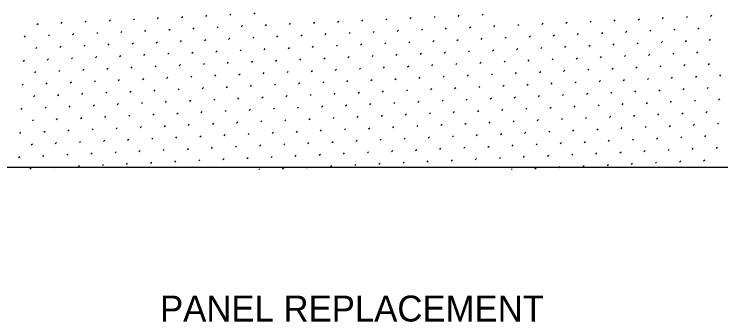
# Model space of a CAD drawing. Extents: x 49991.4 to 50021, y 49987.6 to 50011.4.
# Drawn here: x 50007.726 to 50009.904, y 49993.814 to 49994.763 of the extents above; entities that cross this region are included whole.
import ezdxf

# ---------------------------------------------------------------- set-up
doc = ezdxf.new("R2010")
doc.units = 0
for name, color, linetype in [('Level 1', 7, 'Continuous'), ('Level 10', 7, 'Continuous'), ('Level 2', 7, 'Continuous')]:
    doc.layers.add(name, color=color, linetype=linetype)

msp = doc.modelspace()

# ---------------------------------------------------------------- linework, layer by layer
at = {"layer": 'Level 1'}
msp.add_line((50015.1301, 49994.2903), (50001.3364, 49994.2903), dxfattribs=at)
at = {"layer": 'Level 10'}
for p, q in [((50008.3907, 49994.7596), (50008.3943, 49994.7631)), ((50008.465, 49994.7631), (50008.4685, 49994.7667)), ((50009.1686, 49994.7597), (50009.1721, 49994.7632)), ((50007.9452, 49994.7383), (50007.9487, 49994.7419)), ((50008.0195, 49994.7419), (50008.023, 49994.7454)), ((50008.0937, 49994.7454), (50008.0972, 49994.749)), ((50008.168, 49994.749), (50008.1715, 49994.7525)), ((50008.2422, 49994.7525), (50008.2458, 49994.756)), ((50008.3165, 49994.7561), (50008.32, 49994.7596)), ((50008.7231, 49994.7384), (50008.7266, 49994.7419)), ((50008.7973, 49994.742), (50008.8009, 49994.7455)), ((50008.8716, 49994.7455), (50008.8751, 49994.749)), ((50008.9459, 49994.749), (50008.9494, 49994.7526)), ((50009.0201, 49994.7526), (50009.0236, 49994.7561)), ((50009.0944, 49994.7561), (50009.0979, 49994.7597)), ((50009.501, 49994.7385), (50009.5045, 49994.742)), ((50009.5752, 49994.742), (50009.5788, 49994.7456)), ((50009.6495, 49994.7456), (50009.653, 49994.7491)), ((50009.7237, 49994.7491), (50009.7273, 49994.7526)), ((50009.798, 49994.7527), (50009.8015, 49994.7562)), ((50009.8722, 49994.7562), (50009.8758, 49994.7597)), ((50007.7967, 49994.7313), (50007.8002, 49994.7348)), ((50007.871, 49994.7348), (50007.8745, 49994.7383)), ((50008.2033, 49994.7136), (50008.2069, 49994.7171)), ((50008.2776, 49994.7172), (50008.2811, 49994.7207)), ((50008.3518, 49994.7207), (50008.3554, 49994.7242)), ((50008.4261, 49994.7242), (50008.4296, 49994.7278)), ((50008.5003, 49994.7278), (50008.5039, 49994.7313)), ((50008.5746, 49994.7313), (50008.5781, 49994.7349)), ((50008.6488, 49994.7349), (50008.6524, 49994.7384)), ((50008.9812, 49994.7137), (50008.9847, 49994.7172)), ((50009.0555, 49994.7172), (50009.059, 49994.7208)), ((50009.1297, 49994.7208), (50009.1332, 49994.7243)), ((50009.204, 49994.7243), (50009.2075, 49994.7278)), ((50009.2782, 49994.7279), (50009.2818, 49994.7314)), ((50009.3525, 49994.7314), (50009.356, 49994.7349)), ((50009.4267, 49994.7349), (50009.4303, 49994.7385)), ((50009.7591, 49994.7138), (50009.7626, 49994.7173)), ((50009.8333, 49994.7173), (50009.8369, 49994.7208)), ((50007.7578, 49994.6924), (50007.7613, 49994.6959)), ((50007.8321, 49994.6959), (50007.8356, 49994.6994)), ((50007.9063, 49994.6994), (50007.9098, 49994.703)), ((50007.9806, 49994.703), (50007.9841, 49994.7065)), ((50008.0548, 49994.7065), (50008.0583, 49994.7101)), ((50008.1291, 49994.7101), (50008.1326, 49994.7136)), ((50008.5357, 49994.6924), (50008.5392, 49994.696)), ((50008.6099, 49994.696), (50008.6135, 49994.6995)), ((50008.6842, 49994.6995), (50008.6877, 49994.703)), ((50008.7584, 49994.7031), (50008.762, 49994.7066)), ((50008.8327, 49994.7066), (50008.8362, 49994.7101)), ((50008.907, 49994.7101), (50008.9105, 49994.7137)), ((50009.3136, 49994.6925), (50009.3171, 49994.696)), ((50009.3878, 49994.696), (50009.3914, 49994.6996)), ((50009.4621, 49994.6996), (50009.4656, 49994.7031)), ((50009.5363, 49994.7031), (50009.5399, 49994.7067)), ((50009.6106, 49994.7067), (50009.6141, 49994.7102)), ((50009.6848, 49994.7102), (50009.6884, 49994.7137)), ((50008.0902, 49994.6712), (50008.0937, 49994.6747)), ((50008.1644, 49994.6747), (50008.168, 49994.6783)), ((50008.2387, 49994.6783), (50008.2422, 49994.6818)), ((50008.3129, 49994.6818), (50008.3165, 49994.6853)), ((50008.3872, 49994.6853), (50008.3907, 49994.6889)), ((50008.4614, 49994.6889), (50008.465, 49994.6924)), ((50008.8681, 49994.6712), (50008.8716, 49994.6748)), ((50008.9423, 49994.6748), (50008.9458, 49994.6783)), ((50009.0166, 49994.6783), (50009.0201, 49994.6819)), ((50009.0908, 49994.6819), (50009.0944, 49994.6854)), ((50009.1651, 49994.6854), (50009.1686, 49994.6889)), ((50009.2393, 49994.689), (50009.2429, 49994.6925)), ((50009.6459, 49994.6713), (50009.6495, 49994.6749)), ((50009.7202, 49994.6749), (50009.7237, 49994.6784)), ((50009.7945, 49994.6784), (50009.798, 49994.6819)), ((50009.8687, 49994.6819), (50009.8722, 49994.6855)), ((50007.7932, 49994.657), (50007.7967, 49994.6605)), ((50007.8674, 49994.6605), (50007.8709, 49994.6641)), ((50007.9417, 49994.6641), (50007.9452, 49994.6676)), ((50008.0159, 49994.6676), (50008.0194, 49994.6712)), ((50008.4225, 49994.65), (50008.4261, 49994.6535)), ((50008.4968, 49994.6535), (50008.5003, 49994.6571)), ((50008.571, 49994.6571), (50008.5746, 49994.6606)), ((50008.6453, 49994.6606), (50008.6488, 49994.6642)), ((50008.7195, 49994.6642), (50008.7231, 49994.6677)), ((50008.7938, 49994.6677), (50008.7973, 49994.6712)), ((50009.2004, 49994.6501), (50009.204, 49994.6536)), ((50009.2747, 49994.6536), (50009.2782, 49994.6571)), ((50009.3489, 49994.6571), (50009.3525, 49994.6607)), ((50009.4232, 49994.6607), (50009.4267, 49994.6642)), ((50009.4974, 49994.6642), (50009.501, 49994.6678)), ((50009.5717, 49994.6678), (50009.5752, 49994.6713)), ((50007.977, 49994.6287), (50007.9806, 49994.6323)), ((50008.0513, 49994.6323), (50008.0548, 49994.6358)), ((50008.1255, 49994.6358), (50008.1291, 49994.6394)), ((50008.1998, 49994.6394), (50008.2033, 49994.6429)), ((50008.274, 49994.6429), (50008.2776, 49994.6464)), ((50008.3483, 49994.6464), (50008.3518, 49994.65)), ((50008.7549, 49994.6288), (50008.7584, 49994.6323)), ((50008.8292, 49994.6323), (50008.8327, 49994.6359)), ((50008.9034, 49994.6359), (50008.9069, 49994.6394)), ((50008.9777, 49994.6394), (50008.9812, 49994.643)), ((50009.0519, 49994.643), (50009.0555, 49994.6465)), ((50009.1262, 49994.6465), (50009.1297, 49994.6501)), ((50009.5328, 49994.6289), (50009.5363, 49994.6324)), ((50009.607, 49994.6324), (50009.6106, 49994.636)), ((50009.6813, 49994.636), (50009.6848, 49994.6395)), ((50009.7556, 49994.6395), (50009.7591, 49994.643)), ((50009.8298, 49994.643), (50009.8333, 49994.6466)), ((50007.7543, 49994.6181), (50007.7578, 49994.6216)), ((50007.8285, 49994.6216), (50007.832, 49994.6252)), ((50007.9028, 49994.6252), (50007.9063, 49994.6287)), ((50008.3094, 49994.6075), (50008.3129, 49994.6111)), ((50008.3836, 49994.6111), (50008.3872, 49994.6146)), ((50008.4579, 49994.6146), (50008.4614, 49994.6182)), ((50008.5321, 49994.6182), (50008.5357, 49994.6217)), ((50008.6064, 49994.6217), (50008.6099, 49994.6253)), ((50008.6807, 49994.6253), (50008.6842, 49994.6288)), ((50009.0873, 49994.6076), (50009.0908, 49994.6112)), ((50009.1615, 49994.6112), (50009.1651, 49994.6147)), ((50009.2358, 49994.6147), (50009.2393, 49994.6182)), ((50009.31, 49994.6182), (50009.3136, 49994.6218)), ((50009.3843, 49994.6218), (50009.3878, 49994.6253)), ((50009.4585, 49994.6253), (50009.4621, 49994.6289)), ((50009.8652, 49994.6077), (50009.8687, 49994.6112)), ((50007.7896, 49994.5827), (50007.7931, 49994.5863)), ((50007.8639, 49994.5863), (50007.8674, 49994.5898)), ((50007.9381, 49994.5898), (50007.9417, 49994.5934)), ((50008.0124, 49994.5934), (50008.0159, 49994.5969)), ((50008.0866, 49994.5969), (50008.0902, 49994.6005)), ((50008.1609, 49994.6005), (50008.1644, 49994.604)), ((50008.2351, 49994.604), (50008.2387, 49994.6075)), ((50008.5675, 49994.5828), (50008.571, 49994.5864)), ((50008.6418, 49994.5864), (50008.6453, 49994.5899)), ((50008.716, 49994.5899), (50008.7195, 49994.5934)), ((50008.7903, 49994.5934), (50008.7938, 49994.597)), ((50008.8645, 49994.597), (50008.868, 49994.6005)), ((50008.9388, 49994.6005), (50008.9423, 49994.6041)), ((50009.013, 49994.6041), (50009.0166, 49994.6076)), ((50009.3454, 49994.5829), (50009.3489, 49994.5864)), ((50009.4196, 49994.5864), (50009.4232, 49994.59)), ((50009.4939, 49994.59), (50009.4974, 49994.5935)), ((50009.5681, 49994.5935), (50009.5717, 49994.5971)), ((50009.6424, 49994.5971), (50009.6459, 49994.6006)), ((50009.7167, 49994.6006), (50009.7202, 49994.6041)), ((50009.7909, 49994.6041), (50009.7944, 49994.6077)), ((50008.122, 49994.5616), (50008.1255, 49994.5651)), ((50008.1962, 49994.5651), (50008.1998, 49994.5686)), ((50008.2705, 49994.5686), (50008.274, 49994.5722)), ((50008.3447, 49994.5722), (50008.3483, 49994.5757)), ((50008.419, 49994.5757), (50008.4225, 49994.5793)), ((50008.4932, 49994.5793), (50008.4968, 49994.5828)), ((50008.8999, 49994.5616), (50008.9034, 49994.5652)), ((50008.9741, 49994.5652), (50008.9777, 49994.5687)), ((50009.0484, 49994.5687), (50009.0519, 49994.5723)), ((50009.1226, 49994.5723), (50009.1262, 49994.5758)), ((50009.1969, 49994.5758), (50009.2004, 49994.5793)), ((50009.2711, 49994.5793), (50009.2747, 49994.5829)), ((50009.6778, 49994.5617), (50009.6813, 49994.5652)), ((50009.752, 49994.5652), (50009.7555, 49994.5688)), ((50009.8263, 49994.5688), (50009.8298, 49994.5723)), ((50009.9005, 49994.5723), (50009.9041, 49994.5759)), ((50007.7507, 49994.5439), (50007.7542, 49994.5474)), ((50007.825, 49994.5474), (50007.8285, 49994.5509)), ((50007.8992, 49994.5509), (50007.9028, 49994.5545)), ((50007.9735, 49994.5545), (50007.977, 49994.558)), ((50008.0477, 49994.558), (50008.0513, 49994.5616)), ((50008.4543, 49994.5404), (50008.4579, 49994.5439)), ((50008.5286, 49994.5439), (50008.5321, 49994.5475)), ((50008.6029, 49994.5475), (50008.6064, 49994.551)), ((50008.6771, 49994.551), (50008.6806, 49994.5545)), ((50008.7514, 49994.5546), (50008.7549, 49994.5581)), ((50008.8256, 49994.5581), (50008.8292, 49994.5616)), ((50009.2322, 49994.5405), (50009.2358, 49994.544)), ((50009.3065, 49994.544), (50009.31, 49994.5475)), ((50009.3807, 49994.5475), (50009.3843, 49994.5511)), ((50009.455, 49994.5511), (50009.4585, 49994.5546)), ((50009.5292, 49994.5546), (50009.5328, 49994.5582)), ((50009.6035, 49994.5582), (50009.607, 49994.5617)), ((50008.0088, 49994.5191), (50008.0124, 49994.5227)), ((50008.0831, 49994.5227), (50008.0866, 49994.5262)), ((50008.1573, 49994.5262), (50008.1609, 49994.5297)), ((50008.2316, 49994.5298), (50008.2351, 49994.5333)), ((50008.3058, 49994.5333), (50008.3094, 49994.5368)), ((50008.3801, 49994.5368), (50008.3836, 49994.5404)), ((50008.7867, 49994.5192), (50008.7903, 49994.5227)), ((50008.861, 49994.5227), (50008.8645, 49994.5263)), ((50008.9352, 49994.5263), (50008.9388, 49994.5298)), ((50009.0095, 49994.5298), (50009.013, 49994.5334)), ((50009.0837, 49994.5334), (50009.0873, 49994.5369)), ((50009.158, 49994.5369), (50009.1615, 49994.5404)), ((50009.5646, 49994.5193), (50009.5681, 49994.5228)), ((50009.6389, 49994.5228), (50009.6424, 49994.5263)), ((50009.7131, 49994.5264), (50009.7166, 49994.5299)), ((50009.7874, 49994.5299), (50009.7909, 49994.5334)), ((50009.8616, 49994.5334), (50009.8652, 49994.537)), ((50007.7861, 49994.5085), (50007.7896, 49994.512)), ((50007.8603, 49994.512), (50007.8639, 49994.5156)), ((50007.9346, 49994.5156), (50007.9381, 49994.5191)), ((50008.3412, 49994.4979), (50008.3447, 49994.5015)), ((50008.4155, 49994.5015), (50008.419, 49994.505)), ((50008.4897, 49994.505), (50008.4932, 49994.5086)), ((50008.564, 49994.5086), (50008.5675, 49994.5121)), ((50008.6382, 49994.5121), (50008.6417, 49994.5156)), ((50008.7125, 49994.5157), (50008.716, 49994.5192)), ((50009.1191, 49994.498), (50009.1226, 49994.5015)), ((50009.1933, 49994.5016), (50009.1969, 49994.5051)), ((50009.2676, 49994.5051), (50009.2711, 49994.5086)), ((50009.3418, 49994.5086), (50009.3454, 49994.5122)), ((50009.4161, 49994.5122), (50009.4196, 49994.5157)), ((50009.4904, 49994.5157), (50009.4939, 49994.5193)), ((50009.897, 49994.4981), (50009.9005, 49994.5016)), ((50007.8957, 49994.4767), (50007.8992, 49994.4802)), ((50007.9699, 49994.4802), (50007.9735, 49994.4838)), ((50008.0442, 49994.4838), (50008.0477, 49994.4873)), ((50008.1184, 49994.4873), (50008.122, 49994.4908)), ((50008.1927, 49994.4909), (50008.1962, 49994.4944)), ((50008.2669, 49994.4944), (50008.2705, 49994.4979)), ((50008.6736, 49994.4768), (50008.6771, 49994.4803)), ((50008.7478, 49994.4803), (50008.7514, 49994.4838)), ((50008.8221, 49994.4838), (50008.8256, 49994.4874)), ((50008.8963, 49994.4874), (50008.8999, 49994.4909)), ((50008.9706, 49994.4909), (50008.9741, 49994.4945)), ((50009.0448, 49994.4945), (50009.0484, 49994.498)), ((50009.4515, 49994.4768), (50009.455, 49994.4804)), ((50009.5257, 49994.4804), (50009.5292, 49994.4839)), ((50009.6, 49994.4839), (50009.6035, 49994.4874)), ((50009.6742, 49994.4875), (50009.6777, 49994.491)), ((50009.7485, 49994.491), (50009.752, 49994.4945)), ((50009.8227, 49994.4945), (50009.8263, 49994.4981)), ((50007.7472, 49994.4696), (50007.7507, 49994.4731)), ((50007.8214, 49994.4731), (50007.825, 49994.4767)), ((50008.1538, 49994.452), (50008.1573, 49994.4555)), ((50008.228, 49994.4555), (50008.2316, 49994.459)), ((50008.3023, 49994.459), (50008.3058, 49994.4626)), ((50008.3766, 49994.4626), (50008.3801, 49994.4661)), ((50008.4508, 49994.4661), (50008.4543, 49994.4697)), ((50008.5251, 49994.4697), (50008.5286, 49994.4732)), ((50008.5993, 49994.4732), (50008.6028, 49994.4767)), ((50008.9317, 49994.452), (50008.9352, 49994.4556)), ((50009.0059, 49994.4556), (50009.0095, 49994.4591)), ((50009.0802, 49994.4591), (50009.0837, 49994.4626)), ((50009.1544, 49994.4627), (50009.158, 49994.4662)), ((50009.2287, 49994.4662), (50009.2322, 49994.4697)), ((50009.3029, 49994.4697), (50009.3065, 49994.4733)), ((50009.3772, 49994.4733), (50009.3807, 49994.4768)), ((50009.7096, 49994.4521), (50009.7131, 49994.4556)), ((50009.7838, 49994.4556), (50009.7874, 49994.4592)), ((50009.8581, 49994.4592), (50009.8616, 49994.4627)), ((50007.7825, 49994.4342), (50007.7861, 49994.4378)), ((50007.8568, 49994.4378), (50007.8603, 49994.4413)), ((50007.931, 49994.4413), (50007.9346, 49994.4449)), ((50008.0053, 49994.4449), (50008.0088, 49994.4484)), ((50008.0795, 49994.4484), (50008.0831, 49994.4519)), ((50008.4862, 49994.4308), (50008.4897, 49994.4343)), ((50008.5604, 49994.4343), (50008.564, 49994.4378)), ((50008.6347, 49994.4379), (50008.6382, 49994.4414)), ((50008.7089, 49994.4414), (50008.7125, 49994.4449)), ((50008.7832, 49994.4449), (50008.7867, 49994.4485)), ((50008.8574, 49994.4485), (50008.861, 49994.452)), ((50009.264, 49994.4308), (50009.2676, 49994.4344)), ((50009.3383, 49994.4344), (50009.3418, 49994.4379)), ((50009.4126, 49994.4379), (50009.4161, 49994.4415)), ((50009.4868, 49994.4415), (50009.4903, 49994.445)), ((50009.5611, 49994.445), (50009.5646, 49994.4485)), ((50009.6353, 49994.4486), (50009.6389, 49994.4521)), ((50008.0406, 49994.4095), (50008.0442, 49994.4131)), ((50008.1149, 49994.4131), (50008.1184, 49994.4166)), ((50008.1891, 49994.4166), (50008.1927, 49994.4201)), ((50008.2634, 49994.4201), (50008.2669, 49994.4237)), ((50008.3377, 49994.4237), (50008.3412, 49994.4272)), ((50008.4119, 49994.4272), (50008.4154, 49994.4308)), ((50008.8185, 49994.4096), (50008.8221, 49994.4131)), ((50008.8928, 49994.4131), (50008.8963, 49994.4167)), ((50008.967, 49994.4167), (50008.9706, 49994.4202)), ((50009.0413, 49994.4202), (50009.0448, 49994.4237)), ((50009.1155, 49994.4238), (50009.1191, 49994.4273)), ((50009.1898, 49994.4273), (50009.1933, 49994.4308)), ((50009.5964, 49994.4097), (50009.6, 49994.4132)), ((50009.6707, 49994.4132), (50009.6742, 49994.4167)), ((50009.7449, 49994.4167), (50009.7485, 49994.4203)), ((50009.8192, 49994.4203), (50009.8227, 49994.4238)), ((50009.8934, 49994.4238), (50009.897, 49994.4274)), ((50007.7436, 49994.3953), (50007.7472, 49994.3989)), ((50007.8179, 49994.3989), (50007.8214, 49994.4024)), ((50007.8921, 49994.4024), (50007.8957, 49994.406)), ((50007.9664, 49994.406), (50007.9699, 49994.4095)), ((50008.373, 49994.3883), (50008.3765, 49994.3919)), ((50008.4473, 49994.3919), (50008.4508, 49994.3954)), ((50008.5215, 49994.3954), (50008.5251, 49994.399)), ((50008.5958, 49994.399), (50008.5993, 49994.4025)), ((50008.67, 49994.4025), (50008.6736, 49994.406)), ((50008.7443, 49994.406), (50008.7478, 49994.4096)), ((50009.1509, 49994.3884), (50009.1544, 49994.3919)), ((50009.2252, 49994.3919), (50009.2287, 49994.3955)), ((50009.2994, 49994.3955), (50009.3029, 49994.399)), ((50009.3737, 49994.399), (50009.3772, 49994.4026)), ((50009.4479, 49994.4026), (50009.4514, 49994.4061)), ((50009.5222, 49994.4061), (50009.5257, 49994.4096)), ((50007.9275, 49994.3671), (50007.931, 49994.3706)), ((50008.0017, 49994.3706), (50008.0053, 49994.3742)), ((50008.076, 49994.3742), (50008.0795, 49994.3777)), ((50008.1503, 49994.3777), (50008.1538, 49994.3812)), ((50008.2245, 49994.3812), (50008.228, 49994.3848)), ((50008.2988, 49994.3848), (50008.3023, 49994.3883)), ((50008.7054, 49994.3671), (50008.7089, 49994.3707)), ((50008.7796, 49994.3707), (50008.7832, 49994.3742)), ((50008.8539, 49994.3742), (50008.8574, 49994.3778)), ((50008.9281, 49994.3778), (50008.9317, 49994.3813)), ((50009.0024, 49994.3813), (50009.0059, 49994.3849)), ((50009.0766, 49994.3849), (50009.0802, 49994.3884)), ((50009.4833, 49994.3672), (50009.4868, 49994.3708)), ((50009.5575, 49994.3708), (50009.5611, 49994.3743)), ((50009.6318, 49994.3743), (50009.6353, 49994.3778)), ((50009.706, 49994.3778), (50009.7096, 49994.3814)), ((50009.7803, 49994.3814), (50009.7838, 49994.3849)), ((50009.8545, 49994.3849), (50009.8581, 49994.3885)), ((50007.779, 49994.36), (50007.7825, 49994.3635)), ((50007.8532, 49994.3635), (50007.8568, 49994.3671)), ((50008.2599, 49994.3459), (50008.2634, 49994.3494)), ((50008.3341, 49994.3494), (50008.3376, 49994.353)), ((50008.4084, 49994.353), (50008.4119, 49994.3565)), ((50008.4826, 49994.3565), (50008.4862, 49994.3601)), ((50008.5569, 49994.3601), (50008.5604, 49994.3636)), ((50008.6311, 49994.3636), (50008.6347, 49994.3671)), ((50009.0377, 49994.346), (50009.0413, 49994.3495)), ((50009.112, 49994.3495), (50009.1155, 49994.353)), ((50009.1863, 49994.353), (50009.1898, 49994.3566)), ((50009.2605, 49994.3566), (50009.264, 49994.3601)), ((50009.3348, 49994.3601), (50009.3383, 49994.3637)), ((50009.409, 49994.3637), (50009.4125, 49994.3672)), ((50009.8156, 49994.346), (50009.8192, 49994.3496)), ((50009.8899, 49994.3496), (50009.8934, 49994.3531)), ((50007.8143, 49994.3246), (50007.8179, 49994.3282)), ((50007.8886, 49994.3282), (50007.8921, 49994.3317)), ((50007.9628, 49994.3317), (50007.9664, 49994.3353)), ((50008.0371, 49994.3353), (50008.0406, 49994.3388)), ((50008.1114, 49994.3388), (50008.1149, 49994.3423)), ((50008.1856, 49994.3423), (50008.1891, 49994.3459)), ((50008.5922, 49994.3247), (50008.5958, 49994.3282)), ((50008.6665, 49994.3282), (50008.67, 49994.3318)), ((50008.7407, 49994.3318), (50008.7443, 49994.3353)), ((50008.815, 49994.3353), (50008.8185, 49994.3389)), ((50008.8892, 49994.3389), (50008.8928, 49994.3424)), ((50008.9635, 49994.3424), (50008.967, 49994.346)), ((50009.2959, 49994.3212), (50009.2994, 49994.3248)), ((50009.3701, 49994.3248), (50009.3737, 49994.3283)), ((50009.4444, 49994.3283), (50009.4479, 49994.3319)), ((50009.5186, 49994.3319), (50009.5222, 49994.3354)), ((50009.5929, 49994.3354), (50009.5964, 49994.3389)), ((50009.6671, 49994.3389), (50009.6707, 49994.3425)), ((50009.7414, 49994.3425), (50009.7449, 49994.346)), ((50007.7401, 49994.3211), (50007.7436, 49994.3246)), ((50008.0725, 49994.2999), (50008.076, 49994.3034)), ((50008.1467, 49994.3034), (50008.1502, 49994.307)), ((50008.221, 49994.307), (50008.2245, 49994.3105)), ((50008.2952, 49994.3105), (50008.2987, 49994.3141)), ((50008.3695, 49994.3141), (50008.373, 49994.3176)), ((50008.4437, 49994.3176), (50008.4473, 49994.3212)), ((50008.518, 49994.3212), (50008.5215, 49994.3247)), ((50008.8503, 49994.3), (50008.8539, 49994.3035)), ((50008.9246, 49994.3035), (50008.9281, 49994.3071)), ((50008.9988, 49994.3071), (50009.0024, 49994.3106)), ((50009.0731, 49994.3106), (50009.0766, 49994.3141)), ((50009.1474, 49994.3141), (50009.1509, 49994.3177)), ((50009.2216, 49994.3177), (50009.2251, 49994.3212)), ((50009.6282, 49994.3), (50009.6318, 49994.3036)), ((50009.7025, 49994.3036), (50009.706, 49994.3071)), ((50009.7767, 49994.3071), (50009.7803, 49994.3107)), ((50009.851, 49994.3107), (50009.8545, 49994.3142)), ((50007.7754, 49994.2857), (50007.779, 49994.2893)), ((50007.8497, 49994.2893), (50007.8532, 49994.2928)), ((50007.9239, 49994.2928), (50007.9275, 49994.2964)), ((50007.9982, 49994.2964), (50008.0017, 49994.2999)), ((50008.4806, 49994.2838), (50008.4826, 49994.2858)), ((50008.5533, 49994.2858), (50008.5569, 49994.2893)), ((50008.6276, 49994.2893), (50008.6311, 49994.2929)), ((50008.7018, 49994.2929), (50008.7054, 49994.2964)), ((50008.7761, 49994.2964), (50008.7796, 49994.3)), ((50009.2585, 49994.2838), (50009.2605, 49994.2859)), ((50009.3312, 49994.2859), (50009.3348, 49994.2894)), ((50009.4055, 49994.2894), (50009.409, 49994.293)), ((50009.4797, 49994.293), (50009.4833, 49994.2965)), ((50009.554, 49994.2965), (50009.5575, 49994.3))]:
    msp.add_line(p, q, dxfattribs=at)

# ---------------------------------------------------------------- texts
at = {"layer": 'Level 2'}
msp.add_text('PANEL REPLACEMENT', height=0.08, dxfattribs=at).set_placement((50008.1758, 49993.8155))

doc.saveas('drawing.dxf')
